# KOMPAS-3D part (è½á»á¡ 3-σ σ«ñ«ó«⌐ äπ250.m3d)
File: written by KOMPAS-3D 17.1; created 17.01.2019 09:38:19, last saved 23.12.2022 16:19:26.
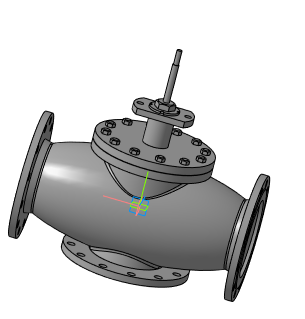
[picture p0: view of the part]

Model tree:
1. Операция без истории:3

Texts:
  ООО АДЛ Групп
